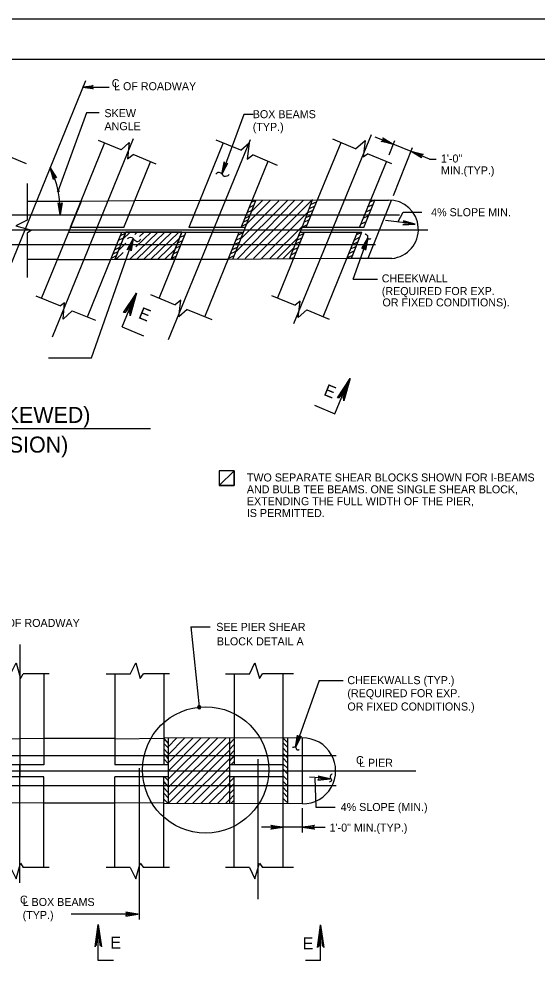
# Model space of a CAD drawing. Extents: x 638091 to 638946, y 298288 to 298882.
# Drawn here: x 638340.6 to 638535, y 298522.4 to 298881.5 of the extents above; entities that cross this region are included whole.
import ezdxf

# ---------------------------------------------------------------- set-up
doc = ezdxf.new("R2010")
doc.units = 0
for name, color, linetype in [('1', 7, 'Continuous'), ('2', 7, 'Continuous'), ('PLT-BNDY', 7, 'Continuous')]:
    doc.layers.add(name, color=color, linetype=linetype)

msp = doc.modelspace()

# ---------------------------------------------------------------- linework, layer by layer
at = {"layer": '1'}
for p, q in [((638379.5, 298799.03), (638382.26, 298801.7)), ((638382.13, 298791.57), (638392.62, 298801.7)), ((638383.91, 298800.79), (638384.85, 298801.7)), ((638384.34, 298796.2), (638390.03, 298801.7)), ((638384.74, 298791.58), (638395.21, 298801.7)), ((638385.72, 298800.03), (638387.44, 298801.7)), ((638387.34, 298791.59), (638397.8, 298801.7)), ((638389.95, 298791.61), (638400.39, 298801.7)), ((638377.81, 298794.9), (638380.56, 298797.55)), ((638392.55, 298791.62), (638400.69, 298799.48)), ((638376.92, 298791.54), (638379.6, 298794.13)), ((638395.16, 298791.63), (638399.04, 298795.38))]:
    msp.add_line(p, q, dxfattribs=at)
for points in [[(638376.44, 298791.54), (638397.53, 298791.65), (638401.58, 298801.7), (638380.58, 298801.7)], [(638415.58, 298706.82), (638421.23, 298706.82), (638421.23, 298712.29), (638415.58, 298712.29)], [(638415.58, 298706.82), (638421.23, 298712.29), (638421.23, 298706.82)]]:
    msp.add_lwpolyline(points, close=True, dxfattribs=at)
at = {"layer": '2'}
for p, q in [((638130.58, 298866.5), (638916.58, 298866.5)), ((638328.83, 298768.7), (638365.58, 298858.55)), ((638364.38, 298856), (638374.28, 298856)), ((638365.88, 298846.4), (638355.08, 298817)), ((638370.53, 298846.4), (638365.88, 298846.4)), ((638424.83, 298845.8), (638416.58, 298823.45)), ((638428.28, 298845.8), (638424.83, 298845.8)), ((638383.28, 298836.65), (638352.98, 298762.4)), ((638378.78, 298832.6), (638370.38, 298836.05)), ((638427.23, 298836.35), (638396.48, 298761.35)), ((638423.63, 298832.45), (638414.48, 298836.2)), ((638472.53, 298838.15), (638443.43, 298767.35)), ((638466.68, 298832.9), (638458.13, 298836.5)), ((638480.81, 298834.65), (638474.06, 298837.35)), ((638479.25, 298830.65), (638481.38, 298836.05)), ((638372.63, 298835.15), (638359.73, 298803.5)), ((638417.03, 298835.15), (638404.13, 298803.5)), ((638461.13, 298835.15), (638448.08, 298803.5)), ((638487.56, 298831.95), (638480.81, 298834.65)), ((638480.93, 298815.5), (638488.03, 298833.41)), ((638343.38, 298827.35), (638336.48, 298830.2)), ((638391.98, 298827.2), (638383.28, 298830.8)), ((638437.43, 298826.75), (638428.13, 298830.65)), ((638480.33, 298827.35), (638471.18, 298831.1)), ((638494.46, 298829.1), (638487.56, 298831.95)), ((638494.46, 298829.1), (638496.86, 298829.1)), ((638379.83, 298803.5), (638389.88, 298828.1)), ((638423.78, 298803.5), (638433.98, 298828.25)), ((638468.18, 298803.5), (638478.23, 298828.1)), ((638343.68, 298806.2), (638343.68, 298820)), ((638363.78, 298813.25), (638343.68, 298813.25)), ((638363.78, 298813.25), (638348.93, 298777.1)), ((638363.78, 298813.25), (638363.63, 298813.25)), ((638383.88, 298813.4), (638363.78, 298813.25)), ((638408.18, 298813.55), (638383.88, 298813.4)), ((638428.28, 298813.55), (638408.33, 298813.55)), ((638421.68, 298794.2), (638441.12, 298813.63)), ((638422.28, 298791.65), (638443.95, 298813.64)), ((638423.9, 298799.48), (638437.91, 298813.49)), ((638424.74, 298801.7), (638429.33, 298813.55)), ((638425.28, 298791.8), (638447.15, 298813.66)), ((638425.96, 298804.86), (638434.69, 298813.59)), ((638426.93, 298811), (638428.73, 298811.9)), ((638429.18, 298813.55), (638427.53, 298812.8)), ((638427.68, 298813.55), (638429.33, 298813.55)), ((638427.8, 298809.59), (638431.78, 298813.57)), ((638452.28, 298813.7), (638427.98, 298813.55)), ((638428.43, 298791.8), (638450.58, 298813.94)), ((638450.48, 298813.7), (638445.9, 298801.7)), ((638451.38, 298811.45), (638449.28, 298810.4)), ((638451.98, 298812.95), (638449.88, 298812.05)), ((638472.38, 298813.7), (638452.28, 298813.7)), ((638469.83, 298803.5), (638473.88, 298813.7)), ((638471.18, 298811.15), (638473.28, 298812.05)), ((638471.48, 298791.95), (638480.18, 298813.7)), ((638473.73, 298813.7), (638472.08, 298812.95)), ((638472.23, 298813.7), (638478.98, 298813.7)), ((638214.67, 298808.15), (638343.68, 298808.15)), ((638343.68, 298808.15), (638483.18, 298808.15)), ((638425.28, 298806.95), (638427.08, 298807.85)), ((638426.03, 298809.05), (638427.98, 298809.95)), ((638431.43, 298791.8), (638448.72, 298809.08)), ((638450.03, 298808), (638447.93, 298807.1)), ((638450.63, 298809.8), (638448.68, 298808.9)), ((638469.53, 298806.95), (638471.63, 298808)), ((638470.58, 298809.35), (638472.53, 298810.25)), ((638482.58, 298805.45), (638484.53, 298809.2)), ((638484.53, 298809.2), (638491.59, 298809.2)), ((638426.03, 298804.85), (638424.08, 298803.95)), ((638426.48, 298806.35), (638424.68, 298805.45)), ((638434.58, 298791.8), (638446.77, 298803.98)), ((638448.53, 298804.4), (638446.58, 298803.5)), ((638449.28, 298806.35), (638447.18, 298805.3)), ((638470.73, 298805.6), (638468.63, 298804.7)), ((638487.38, 298805), (638477.93, 298806.05)), ((638220.08, 298802.6), (638343.68, 298802.6)), ((638343.68, 298802.6), (638493.83, 298802.6)), ((638343.68, 298784.75), (638343.68, 298801.4)), ((638358.98, 298801.7), (638388.45, 298801.7)), ((638379.83, 298803.5), (638359.73, 298803.5)), ((638366.18, 298770.05), (638379.08, 298801.7)), ((638376.53, 298791.65), (638380.58, 298801.7)), ((638378.63, 298800.5), (638380.44, 298801.33)), ((638388.45, 298801.7), (638424.68, 298801.7)), ((638403.08, 298801.7), (638393.03, 298777.1)), ((638401.58, 298801.7), (638397.53, 298791.65)), ((638400.83, 298799.9), (638402.78, 298800.65)), ((638425.43, 298803.5), (638404.13, 298803.5)), ((638410.13, 298770.05), (638423.03, 298801.7)), ((638420.63, 298791.65), (638424.68, 298801.7)), ((638422.58, 298800.65), (638424.53, 298801.55)), ((638447.48, 298801.7), (638437.43, 298777.1)), ((638445.83, 298801.7), (638441.93, 298791.8)), ((638445.38, 298800.35), (638447.18, 298801.25)), ((638445.83, 298801.7), (638469.08, 298801.7)), ((638469.83, 298803.5), (638446.58, 298803.5)), ((638454.53, 298770.05), (638467.43, 298801.7)), ((638465.18, 298791.95), (638469.08, 298801.7)), ((638467.13, 298800.8), (638469.08, 298801.7)), ((638214.3, 298797.05), (638343.68, 298797.05)), ((638343.98, 298797.05), (638474.18, 298797.05)), ((638367.66, 298754.67), (638383.28, 298799.15)), ((638376.98, 298796.75), (638379.08, 298797.65)), ((638377.88, 298798.7), (638379.72, 298799.54)), ((638400.98, 298796.45), (638399.03, 298795.55)), ((638401.88, 298798.55), (638399.93, 298797.65)), ((638421.23, 298797.05), (638423.18, 298797.95)), ((638421.83, 298798.7), (638423.93, 298799.75)), ((638437.28, 298791.8), (638444.93, 298799.45)), ((638445.98, 298798.1), (638444.03, 298797.2)), ((638444.63, 298798.7), (638446.58, 298799.6)), ((638465.78, 298784.15), (638471.33, 298799.45)), ((638465.78, 298797.2), (638467.58, 298798.1)), ((638466.38, 298798.85), (638468.18, 298799.9)), ((638375.18, 298791.95), (638377.13, 298793)), ((638375.78, 298793.6), (638377.73, 298794.5)), ((638376.53, 298795.25), (638378.33, 298796.15)), ((638400.23, 298794.5), (638398.43, 298793.6)), ((638419.13, 298791.95), (638421.23, 298793)), ((638419.73, 298793.6), (638421.83, 298794.65)), ((638420.48, 298795.25), (638422.43, 298796.15)), ((638439.53, 298791.8), (638443.43, 298795.7)), ((638444.33, 298794.05), (638442.38, 298793.15)), ((638445.08, 298795.85), (638443.13, 298794.95)), ((638463.53, 298792.25), (638465.78, 298793.15)), ((638464.13, 298793.75), (638466.38, 298794.8)), ((638465.03, 298795.55), (638466.98, 298796.3)), ((638354.78, 298791.5), (638343.68, 298791.5)), ((638354.78, 298791.5), (638374.88, 298791.5)), ((638374.88, 298791.5), (638399.03, 298791.65)), ((638399.03, 298791.65), (638397.53, 298791.65)), ((638397.68, 298791.95), (638399.48, 298792.7)), ((638399.03, 298791.65), (638418.98, 298791.65)), ((638418.98, 298791.65), (638443.43, 298791.8)), ((638443.28, 298791.8), (638441.93, 298791.8)), ((638442.53, 298791.8), (638443.58, 298792.25)), ((638443.28, 298791.8), (638463.53, 298791.95)), ((638463.53, 298791.95), (638480.33, 298791.95)), ((638465.78, 298784.15), (638474.93, 298784.15)), ((638379.14, 298766.23), (638384.39, 298778.98)), ((638346.83, 298777.85), (638356.13, 298774.1)), ((638389.88, 298778.3), (638399.03, 298774.55)), ((638435.18, 298778), (638444.03, 298774.4)), ((638360.48, 298772.3), (638369.18, 298768.7)), ((638403.53, 298772.75), (638412.83, 298769)), ((638448.38, 298772.6), (638456.78, 298769.15)), ((638379.14, 298766.23), (638387.24, 298762.93)), ((638351.6, 298754.67), (638367.66, 298754.67)), ((638458.97, 298733.7), (638464.22, 298746.45)), ((638451.32, 298736.85), (638458.97, 298733.7)), ((638284.85, 298728.2), (638389.85, 298728.2)), ((638404.88, 298653.87), (638412.25, 298653.87)), ((638404.88, 298653.87), (638408.02, 298623.84)), ((638340.79, 298647.22), (638340.79, 298597.57)), ((638351.89, 298636.27), (638342.14, 298636.27)), ((638349.79, 298636.12), (638349.79, 298602.22)), ((638382.19, 298636.12), (638373.19, 298636.12)), ((638376.49, 298636.12), (638376.49, 298602.22)), ((638396.89, 298636.27), (638387.14, 298636.27)), ((638394.79, 298636.12), (638394.79, 298602.22)), ((638426.89, 298636.12), (638417.89, 298636.12)), ((638421.19, 298636.12), (638421.19, 298602.22)), ((638443.39, 298636.27), (638431.84, 298636.27)), ((638439.49, 298636.12), (638439.49, 298563.67)), ((638452.99, 298633.72), (638444.14, 298608.82)), ((638452.99, 298633.72), (638461.99, 298633.72)), ((638408.1, 298623.12), (638408.1, 298623.45)), ((638349.79, 298611.97), (638330.89, 298611.82)), ((638376.49, 298611.97), (638349.94, 298611.97)), ((638394.79, 298611.97), (638376.49, 298611.82)), ((638446.84, 298612.27), (638394.79, 298612.12)), ((638394.79, 298611.97), (638396.44, 298610.17)), ((638394.79, 298610.17), (638396.44, 298608.52)), ((638396.44, 298608.97), (638399.59, 298612.12)), ((638399.59, 298612.12), (638396.44, 298608.97)), ((638396.44, 298605.97), (638402.59, 298612.12)), ((638396.44, 298602.97), (638405.74, 298612.12)), ((638396.44, 298599.82), (638408.74, 298612.12)), ((638396.44, 298596.82), (638411.89, 298612.12)), ((638396.44, 298593.67), (638414.89, 298612.12)), ((638396.44, 298590.67), (638418.04, 298612.12)), ((638396.44, 298611.97), (638396.44, 298587.67)), ((638396.44, 298587.67), (638419.39, 298610.62)), ((638419.39, 298612.12), (638419.39, 298587.67)), ((638421.04, 298609.72), (638419.39, 298607.92)), ((638419.54, 298610.17), (638421.04, 298611.82)), ((638421.04, 298612.72), (638421.04, 298612.72)), ((638421.04, 298612.57), (638421.04, 298612.57)), ((638439.49, 298612.27), (638441.14, 298610.47)), ((638439.49, 298610.47), (638441.14, 298608.82)), ((638441.14, 298612.27), (638441.14, 298587.52)), ((638446.84, 298587.52), (638446.84, 298612.27)), ((638394.79, 298608.22), (638396.29, 298606.57)), ((638394.79, 298606.27), (638396.44, 298604.47)), ((638399.59, 298587.67), (638419.39, 298607.62)), ((638421.04, 298607.47), (638419.54, 298605.82)), ((638439.49, 298608.52), (638440.99, 298606.87)), ((638439.49, 298606.57), (638441.14, 298604.77)), ((638459.44, 298605.52), (638168.51, 298605.52)), ((638394.79, 298604.47), (638396.44, 298602.67)), ((638402.59, 298587.67), (638419.39, 298604.47)), ((638421.04, 298605.52), (638419.39, 298603.72)), ((638419.99, 298602.22), (638421.04, 298603.27)), ((638421.04, 298602.67), (638421.04, 298602.67)), ((638430.19, 298551.82), (638430.19, 298604.32)), ((638439.49, 298604.77), (638441.14, 298602.97)), ((638439.49, 298602.52), (638441.14, 298600.87)), ((638267.76, 298599.97), (638489.29, 298599.97)), ((638349.79, 298602.22), (638331.49, 298602.22)), ((638340.79, 298557.97), (638340.79, 298602.22)), ((638396.44, 298602.22), (638376.49, 298602.22)), ((638385.64, 298544.17), (638385.64, 298600.87)), ((638405.59, 298587.67), (638419.39, 298601.47)), ((638439.49, 298602.22), (638419.39, 298602.22)), ((638439.64, 298600.42), (638441.14, 298598.77)), ((638349.79, 298597.72), (638331.49, 298597.72)), ((638349.79, 298563.67), (638349.79, 298597.72)), ((638376.49, 298563.67), (638376.49, 298597.72)), ((638396.44, 298597.72), (638376.49, 298597.72)), ((638394.79, 298563.67), (638394.79, 298597.72)), ((638394.79, 298595.77), (638396.44, 298593.97)), ((638396.29, 298596.37), (638395.09, 298597.72)), ((638408.74, 298587.67), (638419.39, 298598.32)), ((638411.74, 298587.67), (638419.39, 298595.32)), ((638439.49, 298597.72), (638419.39, 298597.72)), ((638419.39, 298595.62), (638421.04, 298597.27)), ((638421.19, 298563.67), (638421.19, 298597.72)), ((638440.99, 298596.67), (638439.49, 298598.17)), ((638439.49, 298596.07), (638441.14, 298594.27)), ((638455.53, 298597.22), (638449.45, 298597.56)), ((638451.38, 298597.19), (638451.84, 298586.32)), ((638459.44, 298594.27), (638173.53, 298594.27)), ((638394.79, 298593.52), (638396.29, 298591.87)), ((638414.89, 298587.67), (638419.39, 298592.32)), ((638421.04, 298595.02), (638419.39, 298593.37)), ((638421.04, 298592.92), (638419.39, 298591.27)), ((638439.49, 298593.82), (638440.99, 298592.17)), ((638439.64, 298591.72), (638441.14, 298590.07)), ((638396.29, 298587.82), (638394.79, 298589.32)), ((638394.94, 298591.42), (638396.44, 298589.77)), ((638417.89, 298587.67), (638419.39, 298589.17)), ((638421.04, 298590.82), (638419.39, 298589.02)), ((638421.19, 298588.87), (638419.99, 298587.67)), ((638440.99, 298588.12), (638439.49, 298589.62)), ((638349.79, 298587.82), (638330.89, 298587.97)), ((638376.49, 298587.82), (638349.94, 298587.82)), ((638394.79, 298587.82), (638376.49, 298587.97)), ((638446.84, 298587.52), (638394.79, 298587.67)), ((638396.44, 298587.67), (638396.44, 298587.67)), ((638399.59, 298587.67), (638399.59, 298587.67)), ((638402.74, 298587.52), (638402.74, 298587.52)), ((638404.39, 298587.67), (638404.39, 298587.67)), ((638405.74, 298587.67), (638405.74, 298587.67)), ((638408.74, 298587.67), (638408.74, 298587.67)), ((638411.74, 298587.67), (638411.74, 298587.67)), ((638414.89, 298587.67), (638414.89, 298587.67)), ((638417.89, 298587.67), (638417.89, 298587.67)), ((638446.84, 298587.52), (638446.84, 298587.52)), ((638446.84, 298576.87), (638446.84, 298585.87)), ((638451.84, 298586.32), (638458.99, 298586.32)), ((638446.84, 298578.82), (638431.39, 298578.82)), ((638446.69, 298578.82), (638455.24, 298578.82)), ((638351.89, 298563.67), (638342.14, 298563.67)), ((638382.19, 298563.67), (638373.19, 298563.67)), ((638396.89, 298563.67), (638387.14, 298563.67)), ((638426.89, 298563.67), (638417.89, 298563.67)), ((638443.39, 298563.67), (638431.84, 298563.67)), ((638385.19, 298546.27), (638360.14, 298546.27)), ((638370.22, 298528.9), (638370.22, 298542.4)), ((638453.6, 298528.9), (638453.6, 298542.25)), ((638375.92, 298528.9), (638370.22, 298528.9)), ((638453.6, 298528.9), (638447.9, 298528.9))]:
    msp.add_line(p, q, dxfattribs=at)
for points in [[(638368.13, 298855.55), (638367.98, 298855.85), (638364.38, 298856), (638368.13, 298855.55), (638368.28, 298855.4), (638364.38, 298856), (638367.98, 298856.15), (638367.98, 298856.45), (638364.38, 298856), (638368.28, 298856.6), (638367.98, 298856.45)], [(638466.68, 298832.9), (638470.28, 298836.05), (638469.53, 298829.9), (638471.18, 298831.1)], [(638477.06, 298836.75), (638477.06, 298836.45), (638480.81, 298834.65), (638477.06, 298836.75), (638476.91, 298837.05), (638480.81, 298834.65), (638476.91, 298836), (638476.61, 298835.85), (638480.81, 298834.65), (638476.31, 298835.7), (638476.61, 298835.85)], [(638378.78, 298832.6), (638381.78, 298835.3), (638381.18, 298829.15), (638383.28, 298830.8)], [(638423.63, 298832.45), (638426.78, 298835.15), (638426.03, 298829), (638428.13, 298830.65)], [(638491.31, 298829.85), (638491.31, 298830.15), (638487.56, 298831.95), (638491.31, 298829.85), (638491.46, 298829.55), (638487.56, 298831.95), (638491.46, 298830.6), (638491.76, 298830.75), (638487.56, 298831.95), (638492.06, 298830.9), (638491.76, 298830.75)], [(638353.43, 298821.8), (638353.73, 298822.1), (638352.23, 298825.85), (638353.43, 298821.8), (638353.43, 298821.5), (638352.23, 298825.85), (638354.03, 298822.25), (638354.48, 298822.25), (638352.23, 298825.85), (638354.63, 298822.1), (638354.48, 298822.25)], [(638417.48, 298827.8), (638417.78, 298827.5), (638416.58, 298823.45), (638417.48, 298827.8), (638417.48, 298828.1), (638416.58, 298823.45), (638418.23, 298827.35), (638418.53, 298827.35), (638416.58, 298823.45), (638418.83, 298827.5), (638418.53, 298827.35)], [(638356.43, 298812.35), (638356.13, 298812.2), (638355.98, 298808.15), (638356.43, 298812.35), (638356.73, 298812.65), (638355.98, 298808.15), (638355.68, 298812.2), (638355.38, 298812.35), (638355.98, 298808.15), (638355.23, 298812.65), (638355.38, 298812.35)], [(638343.53, 298806.2), (638339.33, 298804.1), (638345.18, 298802.45), (638343.53, 298801.4)], [(638484.68, 298804.55), (638484.98, 298804.85), (638489.03, 298804.7), (638484.68, 298804.55), (638484.38, 298804.4), (638489.03, 298804.7), (638484.98, 298805.3), (638484.83, 298805.75), (638489.03, 298804.7), (638484.68, 298805.9), (638484.83, 298805.75)], [(638381.3, 298795.38), (638381.63, 298795.45), (638383.3, 298799.18), (638381.3, 298795.38), (638381.07, 298795.14), (638383.3, 298799.18), (638382.02, 298795.18), (638382.27, 298794.96), (638383.3, 298799.18), (638382.52, 298794.73), (638382.27, 298794.96)], [(638469.38, 298795.55), (638469.68, 298795.7), (638471.33, 298799.45), (638469.38, 298795.55), (638469.08, 298795.55), (638471.33, 298799.45), (638470.13, 298795.55), (638470.28, 298795.25), (638471.33, 298799.45), (638470.43, 298794.95), (638470.28, 298795.25)], [(638380.34, 298771.63), (638380.94, 298772.23), (638384.54, 298778.83), (638380.34, 298771.63), (638379.74, 298771.63), (638384.54, 298778.83), (638381.84, 298771.63), (638382.14, 298771.03), (638384.54, 298778.83), (638382.14, 298770.43), (638382.14, 298771.03)], [(638360.48, 298772.3), (638357.03, 298769.15), (638357.63, 298775.3), (638356.13, 298774.1)], [(638403.53, 298772.75), (638400.38, 298770.05), (638401.13, 298776.2), (638399.03, 298774.55)], [(638448.38, 298772.6), (638445.23, 298769.75), (638445.98, 298775.9), (638444.03, 298774.4)], [(638460.47, 298739.7), (638461.07, 298740.3), (638464.67, 298746.9), (638460.47, 298739.7), (638459.87, 298739.7), (638464.67, 298746.9), (638461.97, 298739.7), (638462.27, 298739.1), (638464.67, 298746.9), (638462.27, 298738.5), (638462.27, 298739.1)], [(638337.34, 298636.12), (638339.44, 298640.32), (638341.09, 298634.47), (638342.14, 298636.27)], [(638382.19, 298636.12), (638384.29, 298640.32), (638385.94, 298634.47), (638387.14, 298636.27)], [(638426.89, 298636.12), (638428.99, 298640.32), (638430.64, 298634.47), (638431.84, 298636.27)], [(638446.09, 298612.72), (638445.64, 298612.72), (638444.14, 298608.82), (638446.09, 298612.72), (638446.24, 298612.87), (638444.14, 298608.82), (638445.34, 298612.87), (638445.04, 298613.02), (638444.14, 298608.82), (638444.89, 298613.32), (638445.04, 298613.02)], [(638452.83, 298596.77), (638452.98, 298597.07), (638457.18, 298596.92), (638452.83, 298596.77), (638452.53, 298596.47), (638457.18, 298596.92), (638452.98, 298597.52), (638452.98, 298597.82), (638457.18, 298596.92), (638452.68, 298597.97), (638452.98, 298597.82)], [(638435.14, 298579.27), (638435.29, 298578.97), (638439.49, 298578.82), (638435.14, 298579.27), (638434.99, 298579.57), (638439.49, 298578.82), (638435.29, 298578.52), (638435.14, 298578.22), (638439.49, 298578.82), (638434.99, 298578.07), (638435.14, 298578.22)], [(638451.04, 298578.22), (638450.89, 298578.52), (638446.69, 298578.82), (638451.04, 298578.22), (638451.34, 298578.07), (638446.69, 298578.82), (638450.89, 298578.97), (638451.04, 298579.27), (638446.69, 298578.82), (638451.34, 298579.57), (638451.04, 298579.27)], [(638337.34, 298563.67), (638339.44, 298559.47), (638341.09, 298565.32), (638342.14, 298563.67)], [(638382.19, 298563.67), (638384.29, 298559.47), (638385.94, 298565.32), (638387.14, 298563.67)], [(638426.89, 298563.67), (638428.99, 298559.47), (638430.64, 298565.32), (638431.84, 298563.67)], [(638380.69, 298545.82), (638380.84, 298546.12), (638385.04, 298546.27), (638380.69, 298545.82), (638380.54, 298545.52), (638385.04, 298546.27), (638380.84, 298546.57), (638380.69, 298546.87), (638385.04, 298546.27), (638380.54, 298547.02), (638380.69, 298546.87)], [(638369.02, 298534.3), (638369.62, 298534.6), (638370.22, 298542.4), (638369.02, 298534.3), (638369.02, 298534), (638370.22, 298542.4), (638370.82, 298534.6), (638371.42, 298534.6), (638370.22, 298542.4), (638371.42, 298534), (638371.42, 298534.6)], [(638452.4, 298534), (638453, 298534.3), (638453.6, 298542.1), (638452.4, 298534), (638452.4, 298533.7), (638453.6, 298542.1), (638454.2, 298534.3), (638454.8, 298534.3), (638453.6, 298542.1), (638454.8, 298533.7), (638454.8, 298534.3)]]:
    msp.add_lwpolyline(points, dxfattribs=at)
for centre, radius in [((638355.22, 298817.07), 0.275), ((638408.1, 298623.73), 0.283), ((638410.48, 298600.26), 23.66)]:
    msp.add_circle(centre, radius, dxfattribs=at)
for centre, radius, start, end in [((638320.1, 298809.87), 35.9, 357.1674, 26.5522), ((638479.3, 298802.77), 10.94, 275.2858, 92.0205), ((638408.1, 298623.73), 0.604, 269.6129, 268.6063), ((638446.87, 298599.9), 12.36, 269.8619, 90.1377)]:
    msp.add_arc(centre, radius, start, end, dxfattribs=at)
for points in [[(638419.28, 298823.3), (638418.83, 298822.85), (638417.93, 298822.55), (638417.03, 298822.85), (638416.73, 298823.45), (638415.98, 298823.9), (638415.08, 298824.05), (638414.78, 298823.9), (638414.33, 298823.45)], [(638472.38, 298799.15), (638472.08, 298799.15), (638471.48, 298799.15), (638471.33, 298799.75), (638471.33, 298800.05), (638471.18, 298800.5), (638470.73, 298800.8), (638470.58, 298800.95), (638470.28, 298800.8)], [(638386.04, 298799.04), (638385.74, 298798.59), (638384.69, 298798.14), (638383.94, 298798.59), (638383.49, 298799.19), (638382.89, 298799.64), (638381.84, 298799.64), (638381.54, 298799.49), (638381.24, 298799.19)], [(638443.09, 298608.67), (638443.39, 298608.82), (638443.99, 298608.97), (638444.29, 298608.67), (638444.44, 298608.22), (638444.59, 298607.92), (638445.04, 298607.77), (638445.34, 298607.77), (638445.49, 298607.92)], [(638457.98, 298598.71), (638457.66, 298598.54), (638457.27, 298598.13), (638457.2, 298597.49), (638457.45, 298597.01), (638457.7, 298596.53), (638457.55, 298596.05), (638457.23, 298595.88), (638456.91, 298595.71)]]:
    msp.add_spline(points, degree=3, dxfattribs=at)
at = {"layer": 'PLT-BNDY'}
msp.add_lwpolyline([(638090.58, 298287.5), (638931.58, 298287.5), (638931.58, 298881.5), (638090.58, 298881.5)], close=True, dxfattribs=at)

# ---------------------------------------------------------------- texts
at = {"layer": '2'}
for s, height, p in [('C', 3, (638375.3, 298856.01)), ('L OF ROADWAY', 2.9999, (638376.18, 298854.89)), ('SKEW', 3, (638372.56, 298844.8)), (' BOX BEAMS', 3, (638427.04, 298844.41)), ('ANGLE', 3, (638372.56, 298839.92)), (' (TYP.)', 3, (638427.04, 298839.66)), ('1\'-0"', 3, (638498.7, 298827.81)), ('MIN.(TYP.)', 3, (638498.7, 298823.37)), ('4% SLOPE MIN.', 2.9999, (638495.03, 298807.69)), ('CHEEKWALL', 3, (638476.53, 298782.9)), ('(REQUIRED FOR EXP.', 2.9999, (638476.53, 298778.15)), ('OR FIXED CONDITIONS).', 2.9999, (638476.78, 298773.9)), (' PIER PLAN (SKEWED)', 5.9998, (638280.8, 298730.25)), ('(EXPANSION)', 5.9998, (638306.84, 298719.14)), ('TWO SEPARATE SHEAR BLOCKS SHOWN FOR I-BEAMS', 3, (638425.94, 298708.32)), ('AND BULB TEE BEAMS. ONE SINGLE SHEAR BLOCK, ', 3, (638425.94, 298703.87)), ('EXTENDING THE FULL WIDTH OF THE PIER, ', 3, (638425.94, 298699.43)), ('IS PERMITTED.', 3, (638425.94, 298694.99)), ('L OF ROADWAY', 2.9999, (638332.54, 298653.82)), ('SEE PIER SHEAR ', 2.9999, (638414.48, 298652.35)), ('BLOCK DETAIL A', 2.9999, (638414.69, 298646.93)), ('CHEEKWALLS (TYP.)', 2.9999, (638463.63, 298632.39)), ('(REQUIRED FOR EXP.', 2.9999, (638463.63, 298627.51)), ('OR FIXED CONDITIONS.)', 2.9999, (638463.63, 298622.51)), ('C', 3, (638466.87, 298602.44)), ('L PIER ', 3, (638468, 298601.44)), ('4% SLOPE (MIN.)', 2.9999, (638461.14, 298584.86)), ('1\'-0" MIN.(TYP.)', 2.9999, (638456.97, 298577.15)), ('C', 3, (638340.9, 298550.16)), ('L BOX BEAMS', 2.9999, (638341.9, 298549.29)), ('(TYP.)', 3, (638341.9, 298544.41)), ('E', 4.5, (638374.76, 298533.31)), ('E', 4.5, (638446.86, 298533))]:
    msp.add_text(s, height=height, dxfattribs=at).set_placement(p)
for rotation, p in [(337.7436, (638384.97, 298769.64)), (337.7841, (638454.42, 298740.79))]:
    msp.add_text('E', height=4.5, rotation=rotation, dxfattribs=at).set_placement(p)

doc.saveas('drawing.dxf')
